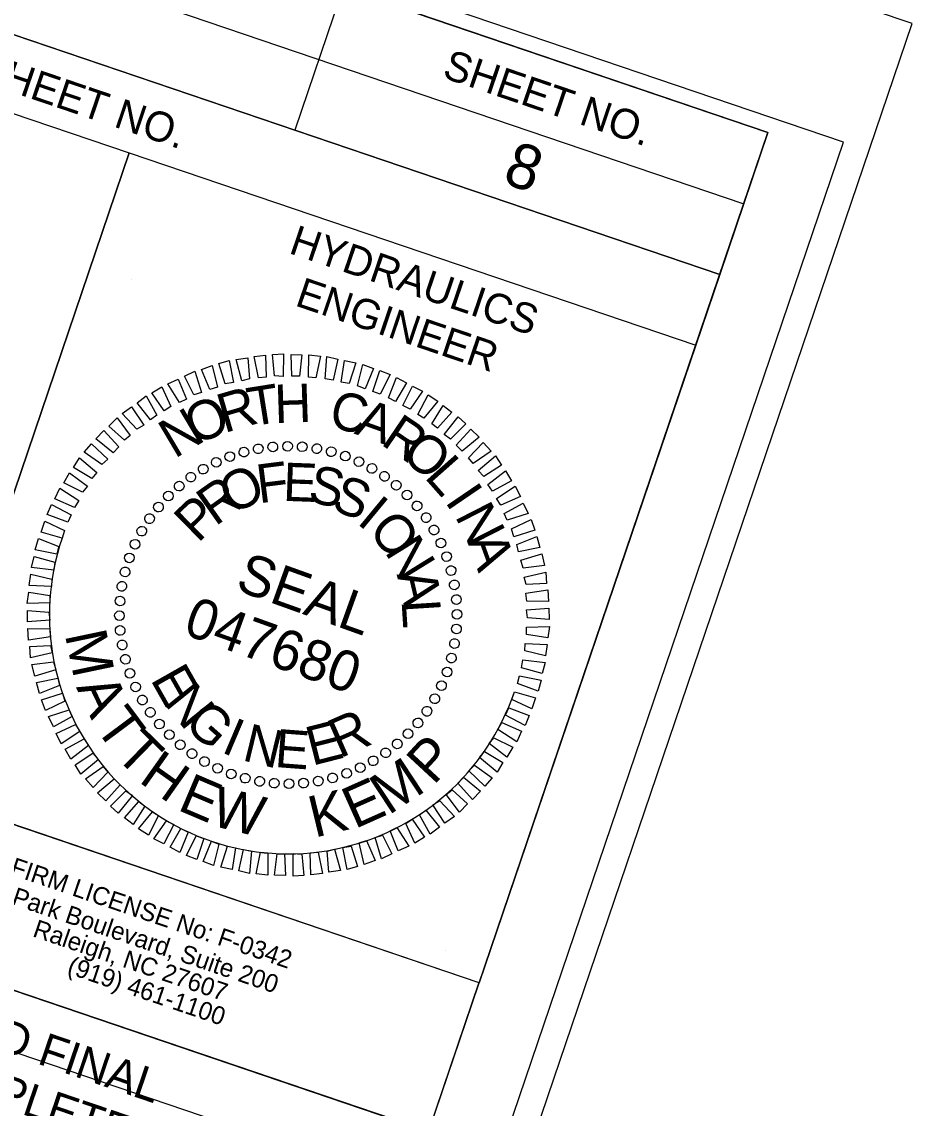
# Model space of a CAD drawing. Extents: x 2298691 to 2299860, y 598939 to 599889.
# Drawn here: x 2299770.4 to 2299859.7, y 599455.3 to 599564.2 of the extents above; entities that cross this region are included whole.
import ezdxf

# ---------------------------------------------------------------- set-up
doc = ezdxf.new("R2010")
doc.units = 0
for name, color, linetype in [('Old_Level_2', 7, 'Continuous'), ('Prop DSN Text', 7, 'Continuous'), ('Scratch_Level_0', 7, 'Continuous'), ('Sheet Block Title CELL', 7, 'Continuous'), ('Sheet Border Standard 30in CELL', 7, 'Continuous'), ('Sheet Data Field CELL', 7, 'Continuous'), ('Sheet Plot Border Inside CELL', 7, 'Continuous'), ('Sheet Plot Border Outside CELL', 7, 'Continuous'), ('Sheet Sticker Exception Certification CELL', 7, 'Continuous')]:
    doc.layers.add(name, color=color, linetype=linetype)

msp = doc.modelspace()

# ---------------------------------------------------------------- linework, layer by layer
at = {"layer": 'Old_Level_2'}
for p, q in [((2299781.37, 599538.38), (2299781.37, 599538.38)), ((2299794.1, 599521.4), (2299794.1, 599521.4)), ((2299795.56, 599521.62), (2299795.56, 599521.62)), ((2299797.01, 599521.7), (2299797.01, 599521.7)), ((2299798.49, 599521.62), (2299798.49, 599521.62)), ((2299799.98, 599521.4), (2299799.98, 599521.4)), ((2299791.24, 599520.66), (2299791.24, 599520.66)), ((2299792.63, 599521.08), (2299792.63, 599521.08)), ((2299801.42, 599521.13), (2299801.42, 599521.13)), ((2299802.83, 599520.68), (2299802.83, 599520.68)), ((2299788.57, 599519.4), (2299788.57, 599519.4)), ((2299789.86, 599520.06), (2299789.86, 599520.06)), ((2299804.21, 599520.11), (2299804.21, 599520.11)), ((2299805.51, 599519.42), (2299805.51, 599519.42)), ((2299787.33, 599518.57), (2299787.33, 599518.57)), ((2299806.75, 599518.67), (2299806.75, 599518.67)), ((2299786.14, 599517.69), (2299786.14, 599517.69)), ((2299807.94, 599517.77), (2299807.94, 599517.77)), ((2299785.07, 599516.66), (2299785.07, 599516.66)), ((2299809.02, 599516.76), (2299809.02, 599516.76)), ((2299784.06, 599515.58), (2299784.06, 599515.58)), ((2299810.05, 599515.7), (2299810.05, 599515.7)), ((2299783.16, 599514.39), (2299783.16, 599514.39)), ((2299810.93, 599514.51), (2299810.93, 599514.51)), ((2299782.42, 599513.14), (2299782.42, 599513.14)), ((2299811.76, 599513.27), (2299811.76, 599513.27)), ((2299781.73, 599511.85), (2299781.73, 599511.85)), ((2299812.42, 599511.97), (2299812.42, 599511.97)), ((2299781.15, 599510.47), (2299781.15, 599510.47)), ((2299813.02, 599510.59), (2299813.02, 599510.59)), ((2299780.71, 599509.06), (2299780.71, 599509.06)), ((2299813.44, 599509.2), (2299813.44, 599509.2)), ((2299780.43, 599507.62), (2299780.43, 599507.62)), ((2299813.77, 599507.74), (2299813.77, 599507.74)), ((2299780.21, 599506.12), (2299780.21, 599506.12)), ((2299813.98, 599506.27), (2299813.98, 599506.27)), ((2299780.14, 599504.65), (2299780.14, 599504.65)), ((2299797.1, 599504.74), (2299797.1, 599504.74)), ((2299814.06, 599504.82), (2299814.06, 599504.82)), ((2299780.22, 599503.2), (2299780.22, 599503.2)), ((2299813.99, 599503.35), (2299813.99, 599503.35)), ((2299780.43, 599501.74), (2299780.43, 599501.74)), ((2299813.76, 599501.86), (2299813.76, 599501.86)), ((2299780.75, 599500.27), (2299780.75, 599500.27)), ((2299813.49, 599500.42), (2299813.49, 599500.42)), ((2299781.17, 599498.88), (2299781.17, 599498.88)), ((2299813.04, 599499), (2299813.04, 599499)), ((2299781.77, 599497.5), (2299781.77, 599497.5)), ((2299812.47, 599497.63), (2299812.47, 599497.63)), ((2299782.44, 599496.21), (2299782.44, 599496.21)), ((2299811.78, 599496.33), (2299811.78, 599496.33)), ((2299783.26, 599494.96), (2299783.26, 599494.96)), ((2299811.04, 599495.08), (2299811.04, 599495.08)), ((2299784.14, 599493.77), (2299784.14, 599493.77)), ((2299810.13, 599493.89), (2299810.13, 599493.89)), ((2299785.17, 599492.71), (2299785.17, 599492.71)), ((2299809.12, 599492.81), (2299809.12, 599492.81)), ((2299786.26, 599491.7), (2299786.26, 599491.7)), ((2299787.45, 599490.8), (2299787.45, 599490.8)), ((2299806.87, 599490.9), (2299806.87, 599490.9)), ((2299808.06, 599491.78), (2299808.06, 599491.78)), ((2299788.69, 599490.05), (2299788.69, 599490.05)), ((2299805.63, 599490.08), (2299805.63, 599490.08)), ((2299789.99, 599489.36), (2299789.99, 599489.36)), ((2299791.36, 599488.79), (2299791.36, 599488.79)), ((2299802.95, 599488.81), (2299802.95, 599488.81)), ((2299804.33, 599489.41), (2299804.33, 599489.41)), ((2299792.78, 599488.35), (2299792.78, 599488.35)), ((2299794.22, 599488.07), (2299794.22, 599488.07)), ((2299795.71, 599487.85), (2299795.71, 599487.85)), ((2299797.18, 599487.78), (2299797.18, 599487.78)), ((2299798.64, 599487.85), (2299798.64, 599487.85)), ((2299800.1, 599488.07), (2299800.1, 599488.07)), ((2299801.56, 599488.39), (2299801.56, 599488.39)), ((2299812.83, 599471.09), (2299812.83, 599471.09))]:
    msp.add_line(p, q, dxfattribs=at)
for points in [[(2299790.78, 599527.91), (2299790.15, 599529.94), (2299791.19, 599530.27), (2299791.62, 599528.06)], [(2299792.46, 599528.23), (2299791.86, 599530.36), (2299793.03, 599530.53), (2299793.2, 599528.41)], [(2299794.1, 599528.53), (2299793.68, 599530.67), (2299794.82, 599530.78), (2299794.9, 599528.58)], [(2299795.73, 599528.73), (2299795.53, 599530.86), (2299796.62, 599530.92), (2299796.59, 599528.65)], [(2299797.47, 599528.7), (2299797.39, 599530.87), (2299798.47, 599530.82), (2299798.22, 599528.7)], [(2299799.14, 599528.6), (2299799.16, 599530.84), (2299800.32, 599530.7), (2299799.87, 599528.53)], [(2299800.8, 599528.43), (2299800.98, 599530.65), (2299802.07, 599530.39), (2299801.6, 599528.27)], [(2299802.4, 599528.1), (2299802.74, 599530.27), (2299803.87, 599530.02), (2299803.2, 599527.94)], [(2299787.63, 599526.81), (2299786.7, 599528.69), (2299787.73, 599529.2), (2299788.39, 599527.05)], [(2299789.24, 599527.36), (2299788.39, 599529.36), (2299789.48, 599529.74), (2299789.99, 599527.57)], [(2299804.05, 599527.72), (2299804.59, 599529.85), (2299805.64, 599529.46), (2299804.8, 599527.43)], [(2299805.57, 599527.16), (2299806.28, 599529.24), (2299807.32, 599528.85), (2299806.33, 599526.87)], [(2299786.19, 599526.05), (2299785.01, 599527.91), (2299786.06, 599528.37), (2299786.88, 599526.38)], [(2299807.14, 599526.53), (2299807.97, 599528.56), (2299808.96, 599528.01), (2299807.86, 599526.14)], [(2299783.29, 599524.32), (2299781.94, 599526), (2299782.86, 599526.72), (2299783.91, 599524.79)], [(2299784.66, 599525.21), (2299783.42, 599527.02), (2299784.41, 599527.62), (2299785.31, 599525.64)], [(2299808.58, 599525.75), (2299809.57, 599527.7), (2299810.57, 599527.18), (2299809.32, 599525.39)], [(2299810.09, 599524.84), (2299811.12, 599526.81), (2299812.12, 599526.19), (2299810.71, 599524.46)], [(2299811.49, 599523.91), (2299812.64, 599525.73), (2299813.52, 599525.07), (2299812.08, 599523.46)], [(2299781.9, 599523.37), (2299780.44, 599524.94), (2299781.38, 599525.62), (2299782.61, 599523.77)], [(2299812.73, 599522.84), (2299814.15, 599524.61), (2299814.91, 599523.92), (2299813.39, 599522.37)], [(2299780.67, 599522.26), (2299779.12, 599523.68), (2299779.93, 599524.5), (2299781.26, 599522.73)], [(2299779.53, 599521), (2299777.8, 599522.41), (2299778.61, 599523.24), (2299780.09, 599521.6)], [(2299813.96, 599521.75), (2299815.4, 599523.36), (2299816.24, 599522.58), (2299814.55, 599521.16)], [(2299778.41, 599519.82), (2299776.62, 599521.06), (2299777.38, 599521.91), (2299778.99, 599520.37)], [(2299815.18, 599520.51), (2299816.66, 599522.04), (2299817.44, 599521.17), (2299815.66, 599519.92)], [(2299777.41, 599518.44), (2299775.57, 599519.53), (2299776.15, 599520.51), (2299777.89, 599519.03)], [(2299816.14, 599519.23), (2299817.88, 599520.7), (2299818.49, 599519.75), (2299816.71, 599518.61)], [(2299817.12, 599517.82), (2299818.9, 599519.18), (2299819.49, 599518.2), (2299817.58, 599517.17)], [(2299776.47, 599517.05), (2299774.58, 599517.98), (2299775.17, 599518.99), (2299776.96, 599517.64)], [(2299775.66, 599515.51), (2299773.68, 599516.4), (2299774.18, 599517.44), (2299776.08, 599516.22)], [(2299818, 599516.42), (2299819.87, 599517.64), (2299820.38, 599516.61), (2299818.44, 599515.74)], [(2299774.98, 599514.03), (2299772.93, 599514.8), (2299773.35, 599515.83), (2299775.31, 599514.77)], [(2299818.77, 599514.91), (2299820.65, 599515.95), (2299821.16, 599514.92), (2299819.07, 599514.24)], [(2299774.41, 599512.44), (2299772.3, 599513.05), (2299772.67, 599514.14), (2299774.67, 599513.21)], [(2299819.5, 599513.38), (2299821.46, 599514.32), (2299821.83, 599513.23), (2299819.73, 599512.59)], [(2299820.03, 599511.81), (2299822.05, 599512.62), (2299822.35, 599511.49), (2299820.21, 599511.07)], [(2299773.9, 599510.83), (2299771.73, 599511.28), (2299772.04, 599512.39), (2299774.1, 599511.62)], [(2299773.57, 599509.23), (2299771.34, 599509.49), (2299771.61, 599510.61), (2299773.7, 599510.04)], [(2299820.42, 599510.22), (2299822.52, 599510.86), (2299822.81, 599509.69), (2299820.65, 599509.43)], [(2299773.34, 599507.6), (2299771.12, 599507.68), (2299771.29, 599508.83), (2299773.37, 599508.34)], [(2299820.77, 599508.53), (2299822.94, 599509.04), (2299823.02, 599507.91), (2299820.95, 599507.79)], [(2299820.94, 599506.94), (2299823.15, 599507.26), (2299823.22, 599506.09), (2299821.02, 599506.13)], [(2299773.2, 599505.94), (2299770.9, 599505.9), (2299771.07, 599507.02), (2299773.2, 599506.69)], [(2299773.19, 599504.23), (2299770.96, 599504.06), (2299770.94, 599505.17), (2299773.1, 599505.01)], [(2299821.01, 599505.24), (2299823.24, 599505.41), (2299823.26, 599504.3), (2299821.1, 599504.46)], [(2299773.25, 599502.53), (2299771.04, 599502.22), (2299770.97, 599503.38), (2299773.17, 599503.35)], [(2299821, 599503.53), (2299823.29, 599503.57), (2299823.13, 599502.45), (2299820.99, 599502.79)], [(2299773.43, 599500.94), (2299771.26, 599500.43), (2299771.18, 599501.56), (2299773.25, 599501.68)], [(2299820.86, 599501.87), (2299823.08, 599501.79), (2299822.9, 599500.64), (2299820.83, 599501.13)], [(2299773.78, 599499.25), (2299771.67, 599498.61), (2299771.39, 599499.78), (2299773.55, 599500.05)], [(2299820.63, 599500.24), (2299822.86, 599499.98), (2299822.58, 599498.86), (2299820.5, 599499.43)], [(2299774.17, 599497.66), (2299772.14, 599496.85), (2299771.85, 599497.98), (2299773.99, 599498.4)], [(2299820.3, 599498.64), (2299822.46, 599498.19), (2299822.16, 599497.08), (2299820.1, 599497.85)], [(2299774.7, 599496.09), (2299772.74, 599495.15), (2299772.36, 599496.24), (2299774.47, 599496.88)], [(2299819.79, 599497.03), (2299821.9, 599496.42), (2299821.53, 599495.33), (2299819.53, 599496.26)], [(2299775.43, 599494.56), (2299773.54, 599493.52), (2299773.04, 599494.55), (2299775.12, 599495.23)], [(2299819.21, 599495.44), (2299821.27, 599494.67), (2299820.85, 599493.64), (2299818.89, 599494.7)], [(2299776.2, 599493.05), (2299774.32, 599491.83), (2299773.82, 599492.86), (2299775.75, 599493.74)], [(2299818.53, 599493.96), (2299820.51, 599493.08), (2299820.02, 599492.03), (2299818.11, 599493.25)], [(2299777.08, 599491.65), (2299775.3, 599490.29), (2299774.71, 599491.28), (2299776.62, 599492.3)], [(2299817.72, 599492.42), (2299819.62, 599491.49), (2299819.03, 599490.48), (2299817.24, 599491.84)], [(2299778.06, 599490.24), (2299776.31, 599488.77), (2299775.71, 599489.72), (2299777.49, 599490.87)], [(2299816.79, 599491.03), (2299818.63, 599489.94), (2299818.05, 599488.96), (2299816.3, 599490.44)], [(2299779.01, 599488.96), (2299777.53, 599487.43), (2299776.76, 599488.3), (2299778.54, 599489.55)], [(2299815.79, 599489.66), (2299817.57, 599488.41), (2299816.82, 599487.56), (2299815.21, 599489.1)], [(2299780.24, 599487.72), (2299778.8, 599486.11), (2299777.96, 599486.89), (2299779.65, 599488.31)], [(2299814.67, 599488.47), (2299816.4, 599487.06), (2299815.59, 599486.23), (2299814.11, 599487.87)], [(2299781.47, 599486.63), (2299780.05, 599484.86), (2299779.28, 599485.55), (2299780.81, 599487.1)], [(2299813.53, 599487.21), (2299815.08, 599485.8), (2299814.27, 599484.97), (2299812.94, 599486.74)], [(2299782.71, 599485.56), (2299781.56, 599483.74), (2299780.68, 599484.4), (2299782.11, 599486.02)], [(2299812.3, 599486.1), (2299813.76, 599484.53), (2299812.82, 599483.86), (2299811.59, 599485.7)], [(2299784.1, 599484.63), (2299783.08, 599482.66), (2299782.08, 599483.28), (2299783.49, 599485.01)], [(2299809.53, 599484.26), (2299810.77, 599482.45), (2299809.79, 599481.86), (2299808.89, 599483.84)], [(2299810.91, 599485.15), (2299812.26, 599483.47), (2299811.34, 599482.75), (2299810.28, 599484.68)], [(2299785.61, 599483.72), (2299784.63, 599481.77), (2299783.63, 599482.29), (2299784.88, 599484.08)], [(2299787.06, 599482.95), (2299786.23, 599480.91), (2299785.24, 599481.46), (2299786.34, 599483.33)], [(2299808, 599483.42), (2299809.19, 599481.56), (2299808.14, 599481.1), (2299807.32, 599483.09)], [(2299788.63, 599482.31), (2299787.92, 599480.23), (2299786.88, 599480.62), (2299787.87, 599482.6)], [(2299790.15, 599481.75), (2299789.6, 599479.62), (2299788.56, 599480.01), (2299789.39, 599482.05)], [(2299804.95, 599482.11), (2299805.81, 599480.11), (2299804.72, 599479.73), (2299804.21, 599481.9)], [(2299806.57, 599482.66), (2299807.5, 599480.78), (2299806.47, 599480.27), (2299805.81, 599482.42)], [(2299791.8, 599481.37), (2299791.46, 599479.21), (2299790.33, 599479.45), (2299791, 599481.54)], [(2299793.4, 599481.04), (2299793.22, 599478.82), (2299792.13, 599479.09), (2299792.6, 599481.21)], [(2299801.74, 599481.24), (2299802.33, 599479.11), (2299801.17, 599478.94), (2299801, 599481.06)], [(2299803.41, 599481.56), (2299804.04, 599479.53), (2299803.01, 599479.2), (2299802.58, 599481.42)], [(2299795.05, 599480.87), (2299795.04, 599478.63), (2299793.88, 599478.78), (2299794.33, 599480.94)], [(2299796.73, 599480.77), (2299796.81, 599478.6), (2299795.72, 599478.65), (2299795.98, 599480.77)], [(2299798.47, 599480.75), (2299798.67, 599478.61), (2299797.58, 599478.55), (2299797.6, 599480.83)], [(2299800.1, 599480.94), (2299800.52, 599478.8), (2299799.37, 599478.69), (2299799.3, 599480.89)]]:
    msp.add_lwpolyline(points, close=True, dxfattribs=at)
for centre, major_axis in [((2299792.65, 599521.07), (-0.128, 0.469)), ((2299794.09, 599521.4), (-0.086, 0.478)), ((2299795.55, 599521.59), (-0.044, 0.484)), ((2299797.03, 599521.66), (-0.002, 0.486)), ((2299798.5, 599521.61), (0.04, 0.484)), ((2299799.97, 599521.42), (0.082, 0.479)), ((2299801.41, 599521.11), (0.124, 0.47)), ((2299789.88, 599520.05), (-0.207, 0.44)), ((2299791.24, 599520.62), (-0.168, 0.456)), ((2299802.82, 599520.67), (0.164, 0.457)), ((2299804.19, 599520.11), (0.204, 0.441)), ((2299787.33, 599518.56), (-0.28, 0.397)), ((2299788.57, 599519.36), (-0.245, 0.42)), ((2299805.5, 599519.43), (0.241, 0.422)), ((2299806.75, 599518.64), (0.277, 0.399)), ((2299786.16, 599517.66), (-0.314, 0.371)), ((2299807.93, 599517.75), (0.311, 0.374)), ((2299785.08, 599516.66), (-0.345, 0.342)), ((2299809.02, 599516.76), (0.342, 0.345)), ((2299784.08, 599515.56), (-0.374, 0.311)), ((2299810.02, 599515.67), (0.371, 0.314)), ((2299783.19, 599514.39), (-0.399, 0.277)), ((2299810.93, 599514.5), (0.397, 0.28)), ((2299782.4, 599513.14), (-0.422, 0.241)), ((2299811.72, 599513.26), (0.42, 0.245)), ((2299781.73, 599511.83), (-0.441, 0.204)), ((2299812.41, 599511.95), (0.44, 0.207)), ((2299781.17, 599510.46), (-0.457, 0.164)), ((2299812.98, 599510.59), (0.456, 0.168)), ((2299780.73, 599509.05), (-0.47, 0.124)), ((2299813.43, 599509.19), (0.469, 0.128)), ((2299813.76, 599507.75), (0.478, 0.086)), ((2299780.41, 599507.61), (-0.479, 0.082)), ((2299780.23, 599506.14), (-0.484, 0.04)), ((2299813.96, 599506.28), (0.484, 0.044)), ((2299780.17, 599504.66), (-0.486, -0.002)), ((2299814.03, 599504.81), (0.486, 0.002)), ((2299813.97, 599503.33), (0.484, -0.04)), ((2299780.24, 599503.19), (-0.484, -0.044)), ((2299780.44, 599501.73), (-0.478, -0.086)), ((2299813.78, 599501.87), (0.479, -0.082)), ((2299780.77, 599500.29), (-0.469, -0.128)), ((2299813.47, 599500.42), (0.47, -0.124)), ((2299813.03, 599499.01), (0.457, -0.164)), ((2299781.22, 599498.88), (-0.456, -0.168)), ((2299781.79, 599497.52), (-0.44, -0.207)), ((2299812.47, 599497.65), (0.441, -0.204)), ((2299782.47, 599496.21), (-0.42, -0.245)), ((2299811.8, 599496.33), (0.422, -0.241)), ((2299783.27, 599494.97), (-0.397, -0.28)), ((2299811.01, 599495.08), (0.399, -0.277)), ((2299784.18, 599493.8), (-0.371, -0.314)), ((2299810.11, 599493.91), (0.374, -0.311)), ((2299785.18, 599492.72), (-0.342, -0.345)), ((2299809.12, 599492.82), (0.345, -0.342)), ((2299786.27, 599491.72), (-0.311, -0.374)), ((2299808.03, 599491.81), (0.314, -0.371)), ((2299787.45, 599490.83), (-0.277, -0.399)), ((2299806.87, 599490.91), (0.28, -0.397)), ((2299788.7, 599490.04), (-0.241, -0.422)), ((2299790.01, 599489.36), (-0.204, -0.441)), ((2299804.32, 599489.42), (0.207, -0.44)), ((2299805.62, 599490.11), (0.245, -0.42)), ((2299791.38, 599488.8), (-0.164, -0.457)), ((2299792.79, 599488.37), (-0.124, -0.47)), ((2299794.23, 599488.05), (-0.082, -0.479)), ((2299800.11, 599488.08), (0.086, -0.478)), ((2299801.55, 599488.4), (0.128, -0.469)), ((2299802.96, 599488.85), (0.168, -0.456)), ((2299795.69, 599487.87), (-0.04, -0.484)), ((2299797.17, 599487.81), (0.002, -0.486)), ((2299798.64, 599487.88), (0.044, -0.484))]:
    msp.add_ellipse(centre, major_axis=major_axis, ratio=0.999708, dxfattribs=at)
at = {"layer": 'Scratch_Level_0'}
msp.add_lwpolyline([(2299002.4, 599823.52), (2298809.46, 599255.41), (2299633.24, 598975.62), (2299795.1, 599452.24), (2299681.46, 599490.84), (2299712.53, 599582.33)], close=True, dxfattribs=at)
msp.add_arc((2299797.1, 599504.74), 23.96, 161.2404, 341.2404, dxfattribs=at)
at = {"layer": 'Sheet Block Title CELL'}
msp.add_lwpolyline([(2299702.61, 599506.47), (2299816.23, 599467.87), (2299811.17, 599452.96), (2299697.54, 599491.55)], close=True, dxfattribs=at)
at = {"layer": 'Sheet Border Standard 30in CELL'}
for p, q in [((2299729.14, 599584.58), (2299842.79, 599545.98)), ((2299726.73, 599577.48), (2299840.38, 599538.88)), ((2299726.73, 599577.48), (2299840.38, 599538.88)), ((2299802.59, 599567.56), (2299797.77, 599553.35)), ((2299840.38, 599538.88), (2299837.97, 599531.78))]:
    msp.add_line(p, q, dxfattribs=at)
for points in [[(2299845.21, 599553.11), (2298993.02, 599842.55), (2298790.42, 599246.02), (2299642.61, 598956.58)], [(2299731.56, 599591.71), (2299845.21, 599553.11), (2299840.38, 599538.88), (2299726.73, 599577.48)], [(2299724.31, 599570.38), (2299781.15, 599551.08), (2299759.45, 599487.16), (2299702.61, 599506.47)], [(2299781.15, 599551.08), (2299837.97, 599531.78), (2299816.26, 599467.86), (2299759.45, 599487.16)]]:
    msp.add_lwpolyline(points, close=True, dxfattribs=at)
at = {"layer": 'Sheet Plot Border Inside CELL'}
msp.add_lwpolyline([(2299852.81, 599552.15), (2298906.02, 599873.72), (2298702.43, 599274.29), (2299649.22, 598952.72)], close=True, dxfattribs=at)
at = {"layer": 'Sheet Plot Border Outside CELL'}
msp.add_lwpolyline([(2299859.69, 599564.04), (2298902.97, 599888.98), (2298690.72, 599264.04), (2299647.44, 598939.1)], close=True, dxfattribs=at)
at = {"layer": 'Sheet Sticker Exception Certification CELL'}
msp.add_line((2299697.54, 599491.55), (2299811.19, 599452.95), dxfattribs=at)

# ---------------------------------------------------------------- texts
at = {"layer": 'Old_Level_2'}
for s, height, rotation, p in [('T', 3.88, 9.0602, (2299793.32, 599523.63)), ('H', 3.85, 1.8599, (2299795.76, 599523.98)), ('R', 3.91, 16.2609, (2299790.67, 599522.96)), ('C', 3.81, 347.4603, (2299801.05, 599523.6)), ('O', 3.93, 23.4622, (2299787.79, 599521.73)), ('A', 3.81, 340.2607, (2299803.64, 599522.94)), ('N', 3.93, 30.6639, (2299785.69, 599520.37)), ('R', 3.83, 325.8615, (2299806.28, 599521.9)), ('O', 3.86, 318.6616, (2299808.26, 599520.69)), ('L', 3.89, 311.4613, (2299810.67, 599518.56)), ('O', 3.93, 25.9217, (2299791.41, 599514.76)), ('F', 3.88, 7.2075, (2299794.16, 599515.93)), ('E', 3.84, 357.8515, (2299796.53, 599516.19)), ('S', 3.81, 348.496, (2299798.97, 599516.11)), ('R', 3.93, 35.2801, (2299789.76, 599513.57)), ('S', 3.81, 339.1408, (2299801.28, 599515.36)), ('I', 3.92, 304.2606, (2299812.74, 599516.14)), ('P', 3.9, 44.6393, (2299788.05, 599511.87)), ('I', 3.86, 320.43, (2299803.88, 599513.98)), ('N', 3.93, 297.0593, (2299813.77, 599514.68)), ('O', 3.89, 311.0739, (2299805, 599513.1)), ('N', 3.92, 301.717, (2299806.71, 599511.1)), ('A', 3.93, 289.8576, (2299815.02, 599512.16)), ('SEAL', 4.049, 340.2404, (2299791.66, 599507.3)), ('A', 3.92, 283.0007, (2299807.97, 599508.82)), ('047680', 4.05, 340.2404, (2299786.42, 599502.87)), ('L', 3.88, 273.6413, (2299808.46, 599506.19)), ('M', 4.16, 281.835, (2299774.68, 599502.79)), ('E', 3.93, 299.5173, (2299783.22, 599498.29)), ('A', 4.18, 295.6499, (2299775.79, 599497.49)), ('N', 3.9, 308.8744, (2299784.55, 599495.92)), ('T', 4.16, 306.7269, (2299777.58, 599493.53)), ('G', 3.86, 318.2307, (2299786.49, 599493.65)), ('I', 3.81, 336.9416, (2299790.27, 599491.02)), ('E', 3.9, 14.3645, (2299799.48, 599489.6)), ('R', 3.93, 23.7218, (2299802.26, 599490.33)), ('T', 4.12, 315.7269, (2299779.57, 599490.62)), ('N', 3.81, 346.2968, (2299792.37, 599490.19)), ('E', 3.83, 355.6522, (2299795.67, 599489.5)), ('P', 4.13, 47.2226, (2299811.67, 599487.58)), ('H', 4.08, 324.7269, (2299782, 599488.05)), ('M', 4.18, 33.4077, (2299807.15, 599484.6)), ('E', 4.05, 336.9683, (2299785.88, 599485.23)), ('W', 4.05, 346.283, (2299789.18, 599483.67)), ('E', 4.18, 24.093, (2299803.76, 599483.24)), ('K', 4.15, 13.5825, (2299799.73, 599482.39))]:
    msp.add_text(s, height=height, rotation=rotation, dxfattribs=at).set_placement(p)
at = {"layer": 'Prop DSN Text'}
for s, p in [('5438 Wade Park Boulevard, Suite 200', (2299756.97, 599479.94)), ('NC FIRM LICENSE No: F-0342', (2299765.18, 599480.08)), ('Raleigh, NC 27607', (2299771.37, 599472.53)), ('(919) 461-1100', (2299774.83, 599468.83))]:
    msp.add_text(s, height=1.8, rotation=341.2404, dxfattribs=at).set_placement(p)
at = {"layer": 'Sheet Border Standard 30in CELL'}
for s, height, p in [('R/W SHEET NO.', 3.0001, (2299757.33, 599561.26)), ('SHEET NO.', 3, (2299812.44, 599558.67)), ('HYDRAULICS', 3, (2299797.05, 599541.05)), ('ENGINEER', 3, (2299797.67, 599535.8))]:
    msp.add_text(s, height=height, rotation=341.2404, dxfattribs=at).set_placement(p)
at = {"layer": 'Sheet Data Field CELL'}
msp.add_text('8', height=4.5, rotation=341.2404, dxfattribs=at).set_placement((2299818.46, 599548.1))
at = {"layer": 'Sheet Sticker Exception Certification CELL'}
for s, p in [('DOCUMENT NOT CONSIDERED FINAL', (2299707.52, 599481.61)), ('UNLESS ALL SIGNATURES COMPLETED', (2299702.94, 599477.59))]:
    msp.add_text(s, height=3.3, rotation=341.2404, dxfattribs=at).set_placement(p)

doc.saveas('drawing.dxf')
